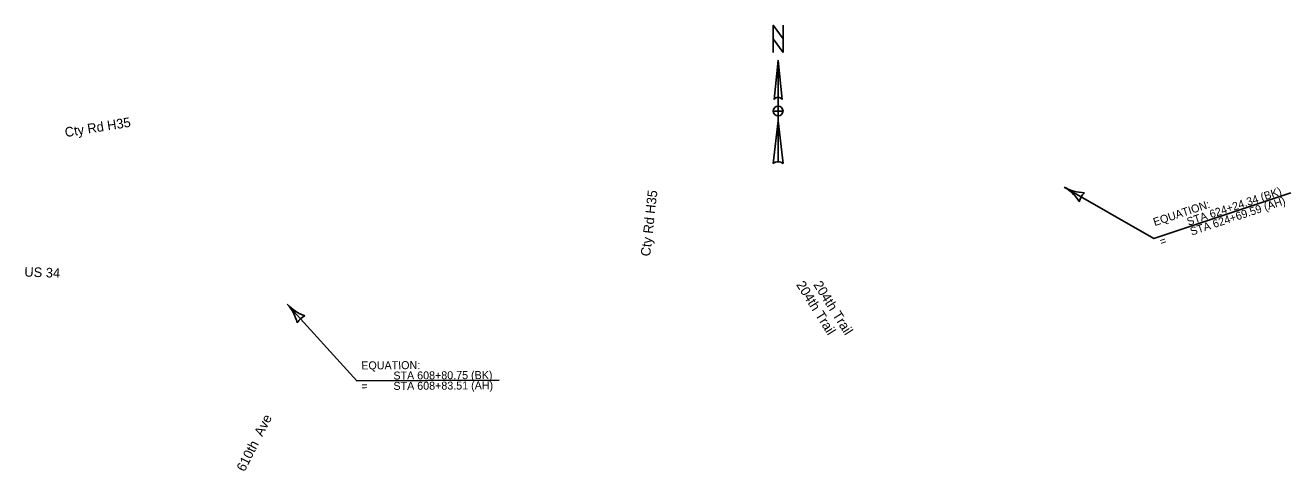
# Model space of a CAD drawing. Extents: x 22712865 to 22760106, y 6235088 to 6238602.
# Drawn here: x 22737990 to 22740456, y 6235181 to 6236050 of the extents above; entities that cross this region are included whole.
import ezdxf

# ---------------------------------------------------------------- set-up
doc = ezdxf.new("R2010")
doc.units = 0
for name, color, linetype in [('Contours Major', 7, 'Continuous'), ('Default', 7, 'Continuous'), ('dsnTextOdd', 7, 'Continuous'), ('Entrance', 7, 'Continuous')]:
    doc.layers.add(name, color=color, linetype=linetype)

msp = doc.modelspace()

# ---------------------------------------------------------------- linework, layer by layer
at = {"layer": 'Contours Major'}
for points in [[(22740013.9, 6235734.9), (22740189.1, 6235634.4), (22740455.5, 6235723.4)], [(22738500.2, 6235506.5), (22738635.6, 6235356.5), (22738913.3, 6235358.3)]]:
    msp.add_lwpolyline(points, dxfattribs=at)
for centre, radius, start, end in [((22739971.6, 6235661.2), 85, 32.0931, 60.1656), ((22740056.2, 6235808.6), 85, 240.1656, 268.2381), ((22740075.7, 6235699.4), 32.8, 132.4322, 167.8989), ((22738437.1, 6235449.5), 85, 13.9811, 42.0536), ((22738563.4, 6235563.4), 85, 222.0536, 250.1261), ((22738548, 6235453.5), 32.8, 114.3202, 149.7869)]:
    msp.add_arc(centre, radius, start, end, dxfattribs=at)
at = {"layer": 'dsnTextOdd'}
for p, q in [((22739456.7, 6235982), (22739464.3, 6235906)), ((22739456.7, 6235982), (22739456.7, 6235784.3)), ((22739449.1, 6235906), (22739449.1, 6235906)), ((22739449.3, 6235906.7), (22739450.8, 6235908.3)), ((22739456.7, 6235873.7), (22739456.7, 6235873.7)), ((22739447.1, 6235780.5), (22739456.7, 6235864.2))]:
    msp.add_line(p, q, dxfattribs=at)
msp.add_lwpolyline([(22739466.2, 6235997.3), (22739447.1, 6236023.9), (22739447.1, 6236050.5), (22739466.2, 6236023.9)], close=True, dxfattribs=at)
for points in [[(22739447.1, 6235997.3), (22739447.1, 6236050.5), (22739466.2, 6236023.9), (22739466.2, 6236050.5)], [(22739449.1, 6235906), (22739456.7, 6235982), (22739456.7, 6235909.8)], [(22739456.7, 6235873.7), (22739456.7, 6235883.2), (22739447.1, 6235883.2)], [(22739466.2, 6235883.2), (22739456.7, 6235883.2), (22739456.7, 6235892.7)], [(22739456.7, 6235784.3), (22739456.7, 6235864.2), (22739466.2, 6235780.5)]]:
    msp.add_lwpolyline(points, dxfattribs=at)
for centre, radius, start, end in [((22739456.7, 6235900.3), 9.51, 90.0204, 143.1257), ((22739456.7, 6235900.3), 9.5, 36.8481, 90.0218), ((22739456.7, 6235883.2), 9.51, 90, 180), ((22739456.7, 6235883.2), 9.51, 180, 270), ((22739456.7, 6235883.2), 9.51, 0, 90), ((22739456.7, 6235883.2), 9.51, 270, 360), ((22739456.7, 6235770.5), 13.8, 89.9894, 133.619), ((22739456.7, 6235770.5), 13.8, 46.4021, 90.0006)]:
    msp.add_arc(centre, radius, start, end, dxfattribs=at)

# ---------------------------------------------------------------- texts
at = {"layer": 'Contours Major'}
for s, height, rotation, p in [('STA 624+24.34 (BK)', 15.601, 18.4767, (22740256.2, 6235659.2)), ('EQUATION:', 15.6, 18.4767, (22740190.6, 6235658.6)), ('STA 624+69.59 (AH)', 15.601, 18.4767, (22740262.6, 6235640.1)), ('=', 15.6, 18.4767, (22740203.4, 6235620.3)), ('EQUATION:', 15.6, 0.3647, (22738644.5, 6235379)), ('STA 608+80.75 (BK)', 15.601, 0.3647, (22738707, 6235359.2)), ('STA 608+83.51 (AH)', 15.601, 0.3647, (22738707.1, 6235339)), ('=', 15.6, 0.3647, (22738644.7, 6235338.6))]:
    msp.add_text(s, height=height, rotation=rotation, dxfattribs=at).set_placement(p)
at = {"layer": 'Default'}
for s, rotation, p in [('Cty Rd H35', 9.1277, (22738068.2, 6235832.1)), ('Cty Rd H35', 83.6546, (22739207.3, 6235598.9)), ('US 34', 357.8939, (22737987.6, 6235560.2)), ('610th  Ave', 63.2699, (22738417, 6235178.2))]:
    msp.add_text(s, height=18.75, rotation=rotation, dxfattribs=at).set_placement(p)
at = {"layer": 'dsnTextOdd'}
msp.add_text('204th Trail', height=18.75, rotation=302.118, dxfattribs=at).set_placement((22739491.2, 6235544.5))
at = {"layer": 'Entrance'}
msp.add_text('204th Trail', height=18.75, rotation=302.118, dxfattribs=at).set_placement((22739524.7, 6235544.5))

doc.saveas('drawing.dxf')
